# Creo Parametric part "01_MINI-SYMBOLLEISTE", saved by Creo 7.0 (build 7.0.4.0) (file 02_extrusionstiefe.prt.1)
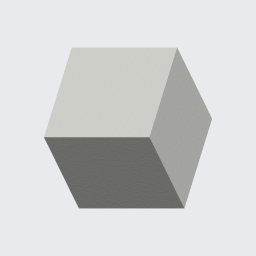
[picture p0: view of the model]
Units: millimeter Kilogram Sec (mmKs); MM, KILOGRAM, SECS
Materials in the file: S235JRG2

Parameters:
  PTC_MATERIAL_NAME = "S235JRG2"
  BENENNUNG = "Symbolleiste"
  DATUM = "XX.XX.XX"
  ERSTELLER = "ARINDA"
  TEILETYP = "Fertigungsteil"
  SELECT_EN_NAME = "S235JRG2"
  SELECT_DIN_NAME = "RSt37-2"
  SELECT_DIN_NUMBER = "1.0038"
  SELECT_ASTM_NAME = "A 283 M Grade 2"
  MATERIAL_GROUP = "ME_ST_Baustahl"
  STANDARD_EN_DELIVERYSPEC = "DIN EN 10025"
  STANDARD_DIN_DELIVERYSPEC = "DIN 17100"

Other parameters: MASSE

Created from: ARINDA-STARTTEIL.PRT

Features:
  1. coordinate system "CS0"
  2. datum plane "DTM1", "T_RECHTS_Y-Z"
  3. datum plane "DTM2", "T_OBEN_X-Z"
  4. datum plane "DTM3", "T_VORNE_X-Y"
  5. datum axis "T_X-ACHSE"
  6. datum axis "A_1"
  7. datum axis "A_2"
  8. extrusion "Profil 1"

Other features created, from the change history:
  sketch "Skizze 1"
  feature "Profil 2"

Other named items: T_BASIC, T_Y-ACHSE, T_Z-ACHSE, DATUM_TAG_A, GP0, DRF1, VORNE, ANNOT_LAYER_STATE0001

Layers: 00_STD-ACHSEN, 00_STD-EBENEN, 00_STD-KOORDSYS, 01_KURVEN, FLAECHEN, KURVENELEMENTE, SAMMELFLÄCHEN, VOLUMENGEOMETRIE

Notes: �⫽ | 0.1Ⓜ | A

Surfaces: 6 plane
